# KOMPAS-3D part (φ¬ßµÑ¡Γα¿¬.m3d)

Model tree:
1. Эскиз:1
2. Операция выдавливания:1
     Расстояние 1 = 2.2
3. Эскиз:2
4. Вырезать элемент выдавливания:9
     Расстояние 1 = 2.2
5. Массив по концентрической сетке:6  (with: Вырезать элемент выдавливания:9)  (labels: Экземпляр ( 1, 1 ); Экземпляр ( 1, 2 ); Экземпляр ( 1, 3 ); Экземпляр ( 1, 4 ))
     N 2 = 10; Шаг 2 = 360
6. Эскиз:16
7. Операция выдавливания:6
     Расстояние 1 = 1
8. Эскиз:18
9. Операция выдавливания:7
     Расстояние 1 = 1
10. Массив по концентрической сетке:7  (with: Операция выдавливания:7)  (labels: Экземпляр ( 1, 1 ); Экземпляр ( 1, 2 ); Экземпляр ( 1, 3 ); Экземпляр ( 1, 4 ))
     N 2 = 10; Шаг 2 = 360
11. Скругление:1
     Радиус = 0.1
12. Скругление:2
     Радиус = 0.1
13. Эскиз:20
14. Операция выдавливания:9
     Расстояние 1 = 2.8
15. Эскиз:21
16. Операция выдавливания:10
     Расстояние 1 = 3.6
17. Эскиз:22
18. Вырезать элемент выдавливания:10
     Расстояние 1 = 5
19. Эскиз:23
20. Отверстие:5
21. Эскиз:24
22. Вырезать элемент выдавливания:11
     Расстояние 1 = 2
23. Скругление:3
     Радиус = 0.2
24. Скругление:4
     Радиус = 0.2
25. Скругление:5
     Радиус = 1
26. Смещенная плоскость:2
     Расстояние = 11
27. Эскиз:25
28. Вырезать элемент выдавливания:12
     Расстояние 1 = 2

Referenced files in C:\Program Files\ASCON\KOMPAS-3D V13 Home\Sys\: holelib.lfr
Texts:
  Сплав АЛ8  ГОСТ 1583-93
  Отверстие 01
  stalker61
  (вариант 1)
  Номер 1
  Номер 2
